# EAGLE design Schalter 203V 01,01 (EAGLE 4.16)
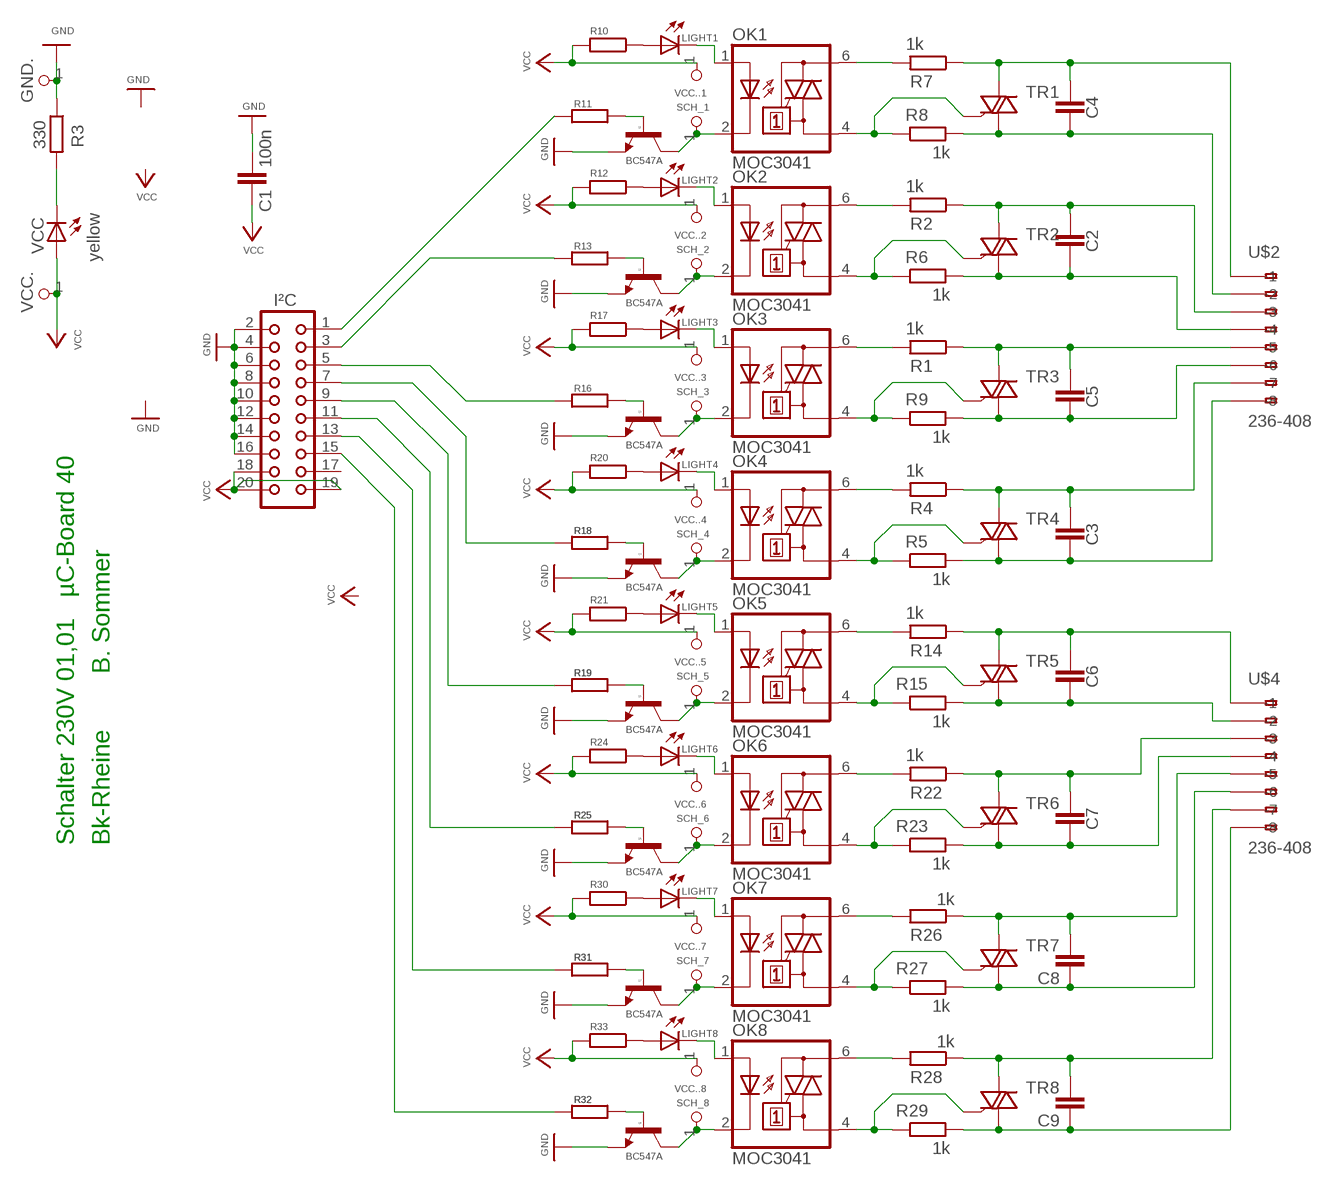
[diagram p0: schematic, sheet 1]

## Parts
C1  100n  C-EU025-030X050  [C025-030X050]
C2  C-EU075-052X106  [C075-052X106]
C3  C-EU075-052X106  [C075-052X106]
C4  C-EU075-052X106  [C075-052X106]
C5  C-EU075-052X106  [C075-052X106]
C6  C-EU075-052X106  [C075-052X106]
C7  C-EU075-052X106  [C075-052X106]
C8  C-EU075-052X106  [C075-052X106]
C9  C-EU075-052X106  [C075-052X106]
GND.  PINHD-1X1  [1X01]
I²C  CON20  [CON20]
LIGHT1  LED3MM  [LED3MM]
LIGHT2  LED3MM  [LED3MM]
LIGHT3  LED3MM  [LED3MM]
LIGHT4  LED3MM  [LED3MM]
LIGHT5  LED3MM  [LED3MM]
LIGHT6  LED3MM  [LED3MM]
LIGHT7  LED3MM  [LED3MM]
LIGHT8  LED3MM  [LED3MM]
OK1  MOC3041  IL410  [DIL06]
OK2  MOC3041  IL410  [DIL06]
OK3  MOC3041  IL410  [DIL06]
OK4  MOC3041  IL410  [DIL06]
OK5  MOC3041  IL410  [DIL06]
OK6  MOC3041  IL410  [DIL06]
OK7  MOC3041  IL410  [DIL06]
OK8  MOC3041  IL410  [DIL06]
Q1  BC547A  [TO92]
Q2  BC547A  [TO92]
Q3  BC547A  [TO92]
Q4  BC547A  [TO92]
Q5  BC547A  [TO92]
Q6  BC547A  [TO92]
Q7  BC547A  [TO92]
Q8  BC547A  [TO92]
R1  1k  R-EU_0204/7  [0204/7]
R2  1k  R-EU_0204/7  [0204/7]
R3  330  R-EU_0204/7  [0204/7]
R4  1k  R-EU_0204/7  [0204/7]
R5  1k  R-EU_0204/7  [0204/7]
R6  1k  R-EU_0204/7  [0204/7]
R7  1k  R-EU_0204/7  [0204/7]
R8  1k  R-EU_0204/7  [0204/7]
R9  1k  R-EU_0204/7  [0204/7]
R10  R-EU_0204/7  [0204/7]
R11  R-EU_0204/7  [0204/7]
R12  R-EU_0204/7  [0204/7]
R13  R-EU_0204/7  [0204/7]
R14  1k  R-EU_0204/7  [0204/7]
R15  1k  R-EU_0204/7  [0204/7]
R16  R-EU_0204/7  [0204/7]
R17  R-EU_0204/7  [0204/7]
R18  R-EU_0204/7  [0204/7]
R19  R-EU_0204/7  [0204/7]
R20  R-EU_0204/7  [0204/7]
R21  R-EU_0204/7  [0204/7]
R22  1k  R-EU_0204/7  [0204/7]
R23  1k  R-EU_0204/7  [0204/7]
R24  R-EU_0204/7  [0204/7]
R25  R-EU_0204/7  [0204/7]
R26  1k  R-EU_0204/7  [0204/7]
R27  1k  R-EU_0204/7  [0204/7]
R28  1k  R-EU_0204/7  [0204/7]
R29  1k  R-EU_0204/7  [0204/7]
R30  R-EU_0204/7  [0204/7]
R31  R-EU_0204/7  [0204/7]
R32  R-EU_0204/7  [0204/7]
R33  R-EU_0204/7  [0204/7]
SCH_1  PINHD-1X1  [1X01]
SCH_2  PINHD-1X1  [1X01]
SCH_3  PINHD-1X1  [1X01]
SCH_4  PINHD-1X1  [1X01]
SCH_5  PINHD-1X1  [1X01]
SCH_6  PINHD-1X1  [1X01]
SCH_7  PINHD-1X1  [1X01]
SCH_8  PINHD-1X1  [1X01]
TR1  BT138  [TO220XL]
TR2  BT138  [TO220XL]
TR3  BT138  [TO220XL]
TR4  BT138  [TO220XL]
TR5  BT138  [TO220XL]
TR6  BT138  [TO220XL]
TR7  BT138  [TO220XL]
TR8  BT138  [TO220XL]
U$2  236-408  [236-408]
U$4  236-408  [236-408]
VCC  yellow  LED3MM  [LED3MM]
VCC.  PINHD-1X1  [1X01]
VCC..1  PINHD-1X1  [1X01]
VCC..2  PINHD-1X1  [1X01]
VCC..3  PINHD-1X1  [1X01]
VCC..4  PINHD-1X1  [1X01]
VCC..5  PINHD-1X1  [1X01]
VCC..6  PINHD-1X1  [1X01]
VCC..7  PINHD-1X1  [1X01]
VCC..8  PINHD-1X1  [1X01]

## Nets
GND: C1.2 GND..1 I²C.2 I²C.4 I²C.6 I²C.8 I²C.10 I²C.12 I²C.14 I²C.16 Q1.1(E) Q2.1(E) Q3.1(E) Q4.1(E) Q5.1(E) Q6.1(E) Q7.1(E) Q8.1(E) R3.1
N$1: R3.2 VCC.K(C)
N$2: LIGHT2.A R12.1
N$3: OK4.2(C) Q4.3(C) SCH_4.1
N$4: LIGHT2.K(C) OK2.1(A)
N$5: OK2.2(C) Q1.3(C) SCH_2.1
N$6: Q1.2(B) R13.1
N$7: OK2.6(A2) R2.2
N$8: OK2.4(A1) R6.1 TR2.G
N$9: OK1.6(A2) R7.2
N$10: C2.1 R6.2 TR2.A1 U$2.A4(-4)
N$11: C2.2 R2.1 TR2.A2 U$2.A3(-3)
N$12: OK1.4(A1) R8.1 TR1.G
N$13: C4.1 R8.2 TR1.A1 U$2.A2(-2)
N$14: OK3.6(A2) R1.2
N$15: C4.2 R7.1 TR1.A2 U$2.A1(-1)
N$16: C5.2 R1.1 TR3.A2 U$2.A5(-5)
N$17: C5.1 R9.2 TR3.A1 U$2.A6(-6)
N$18: OK3.4(A1) R9.1 TR3.G
N$19: LIGHT1.K(C) OK1.1(A)
N$20: LIGHT1.A R10.1
N$21: OK1.2(C) Q2.3(C) SCH_1.1
N$22: Q2.2(B) R11.1
N$23: OK5.6(A2) R14.2
N$24: OK4.6(A2) R4.2
N$25: OK4.4(A1) R5.1 TR4.G
N$26: OK5.4(A1) R15.1 TR5.G
N$28: C6.2 R14.1 TR5.A2 U$4.A1(-1)
N$29: C6.1 R15.2 TR5.A1 U$4.A2(-2)
N$30: I²C.1 R11.2
N$31: I²C.3 R13.2
N$32: C3.2 R4.1 TR4.A2 U$2.A7(-7)
N$33: C3.1 R5.2 TR4.A1 U$2.A8(-8)
N$34: LIGHT3.A R17.1
N$35: LIGHT3.K(C) OK3.1(A)
N$36: Q4.2(B) R18.1
N$37: Q3.2(B) R16.1
N$38: OK3.2(C) Q3.3(C) SCH_3.1
N$39: I²C.5 R16.2
N$40: OK5.2(C) Q5.3(C) SCH_5.1
N$41: Q5.2(B) R19.1
N$42: I²C.7 R18.2
N$43: I²C.9 R19.2
N$44: LIGHT4.A R20.1
N$45: LIGHT4.K(C) OK4.1(A)
N$46: LIGHT5.A R21.1
N$47: LIGHT5.K(C) OK5.1(A)
N$48: OK6.6(A2) R22.2
N$49: C7.2 R22.1 TR6.A2 U$4.A3(-3)
N$50: OK6.4(A1) R23.1 TR6.G
N$51: C7.1 R23.2 TR6.A1 U$4.A4(-4)
N$52: LIGHT6.A R24.1
N$53: OK7.6(A2) R26.2
N$54: C8.2 R26.1 TR7.A2 U$4.A5(-5)
N$55: OK7.4(A1) R27.1 TR7.G
N$56: C8.1 R27.2 TR7.A1 U$4.A6(-6)
N$57: LIGHT6.K(C) OK6.1(A)
N$58: Q6.2(B) R25.1
N$59: OK6.2(C) Q6.3(C) SCH_6.1
N$60: OK8.6(A2) R28.2
N$61: C9.2 R28.1 TR8.A2 U$4.A7(-7)
N$62: OK8.4(A1) R29.1 TR8.G
N$63: C9.1 R29.2 TR8.A1 U$4.A8(-8)
N$64: LIGHT7.A R30.1
N$65: LIGHT8.A R33.1
N$66: LIGHT7.K(C) OK7.1(A)
N$67: Q7.2(B) R31.1
N$68: OK7.2(C) Q7.3(C) SCH_7.1
N$69: LIGHT8.K(C) OK8.1(A)
N$70: OK8.2(C) Q8.3(C) SCH_8.1
N$71: Q8.2(B) R32.1
N$72: I²C.13 R31.2
N$73: I²C.15 R32.2
N$74: I²C.11 R25.2
VCC: C1.1 I²C.18 I²C.19 I²C.20 R10.2 R12.2 R17.2 R20.2 R21.2 R24.2 R30.2 R33.2 VCC..1 VCC..1.1 VCC..2.1 VCC..3.1 VCC..4.1 VCC..5.1 VCC..6.1 VCC..7.1 VCC..8.1 VCC.A
Unconnected: I²C.17 U$2.B1(B-1) U$2.B2(B-2) U$2.B3(B-3) U$2.B4(B-4) U$2.B5(B-5) U$2.B6(B-6) U$2.B7(B-7) U$2.B8(B-8) U$4.B1(B-1) U$4.B2(B-2) U$4.B3(B-3) U$4.B4(B-4) U$4.B5(B-5) U$4.B6(B-6) U$4.B7(B-7) U$4.B8(B-8)

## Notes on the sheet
- Schalter 230V 01,01   µC-Board 40 | Bk-Rheine        B. Sommer

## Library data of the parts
C1-C9 = rcl:C-EU: CAPACITOR, European symbol
GND. SCH_1-SCH_8 VCC. VCC..1-VCC..8 = pinhead 02:PINHD-1X1: PIN HEADER
I²C = con-harting:CON20: CONNECTOR
LIGHT1-LIGHT8 VCC = led:LED: LED
OK1-OK8 = optocoupler:IL410: SIEMENS OPTO COUPLER
Q1-Q8 = transistor-npn:BC547*: NPN Transistor
R1-R33 = rcl:R-EU_: RESISTOR, European symbol
TR1-TR8 = triac:BT138
U$2 U$4 = con-wago255:236-408

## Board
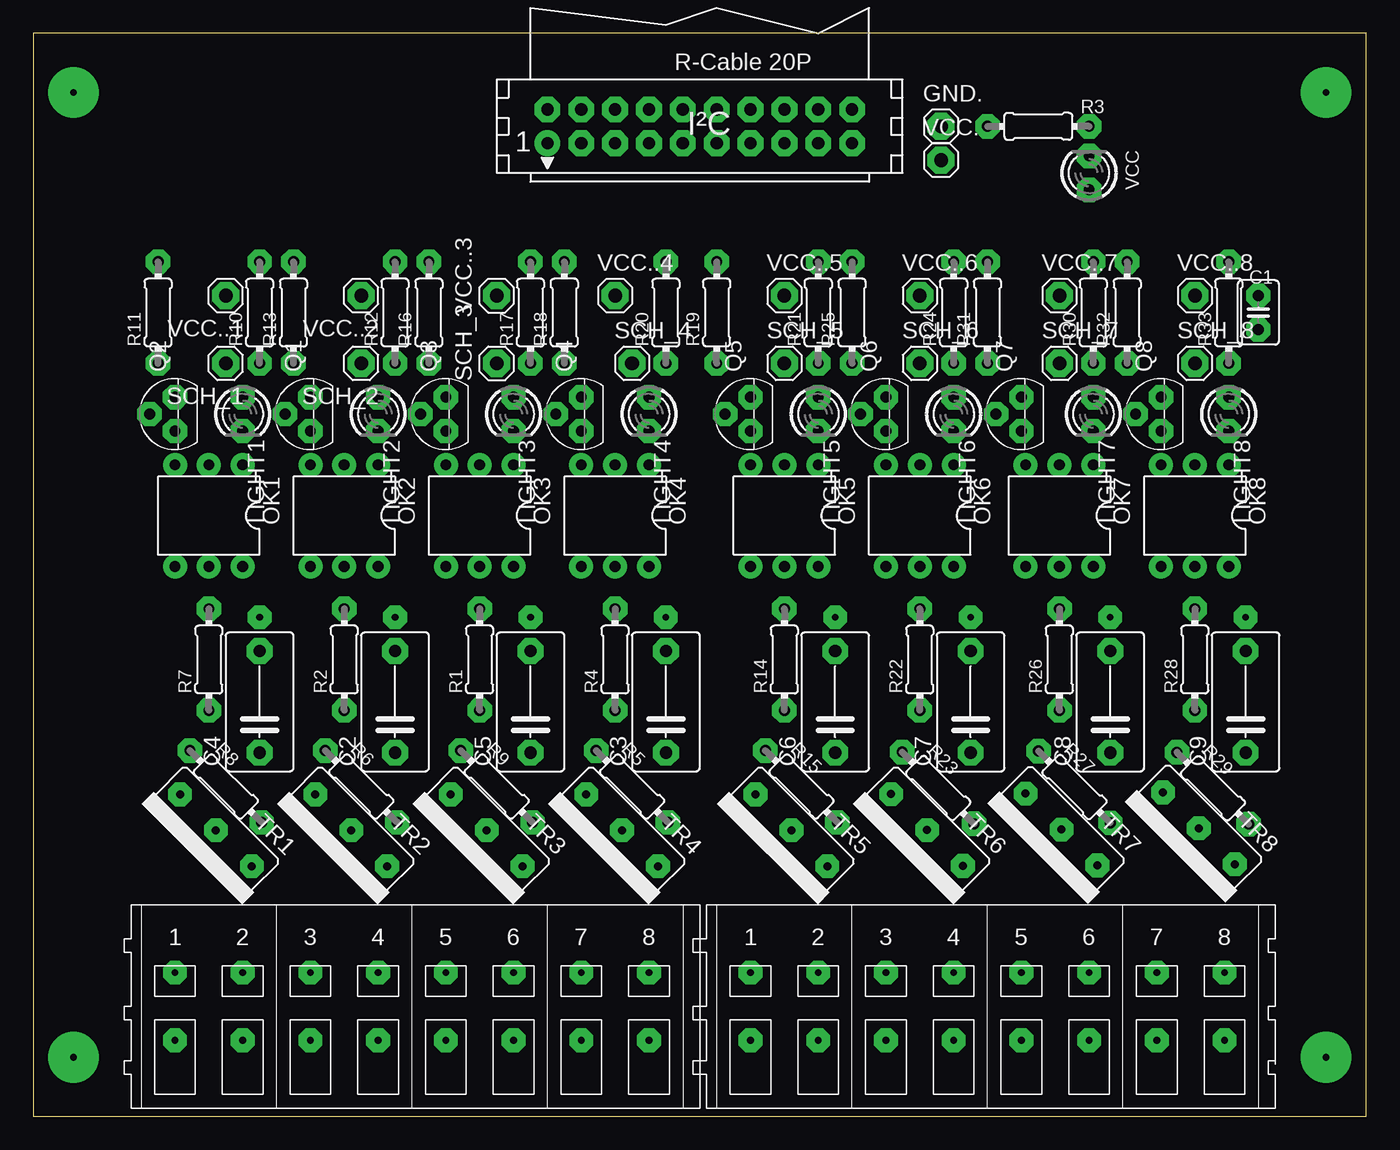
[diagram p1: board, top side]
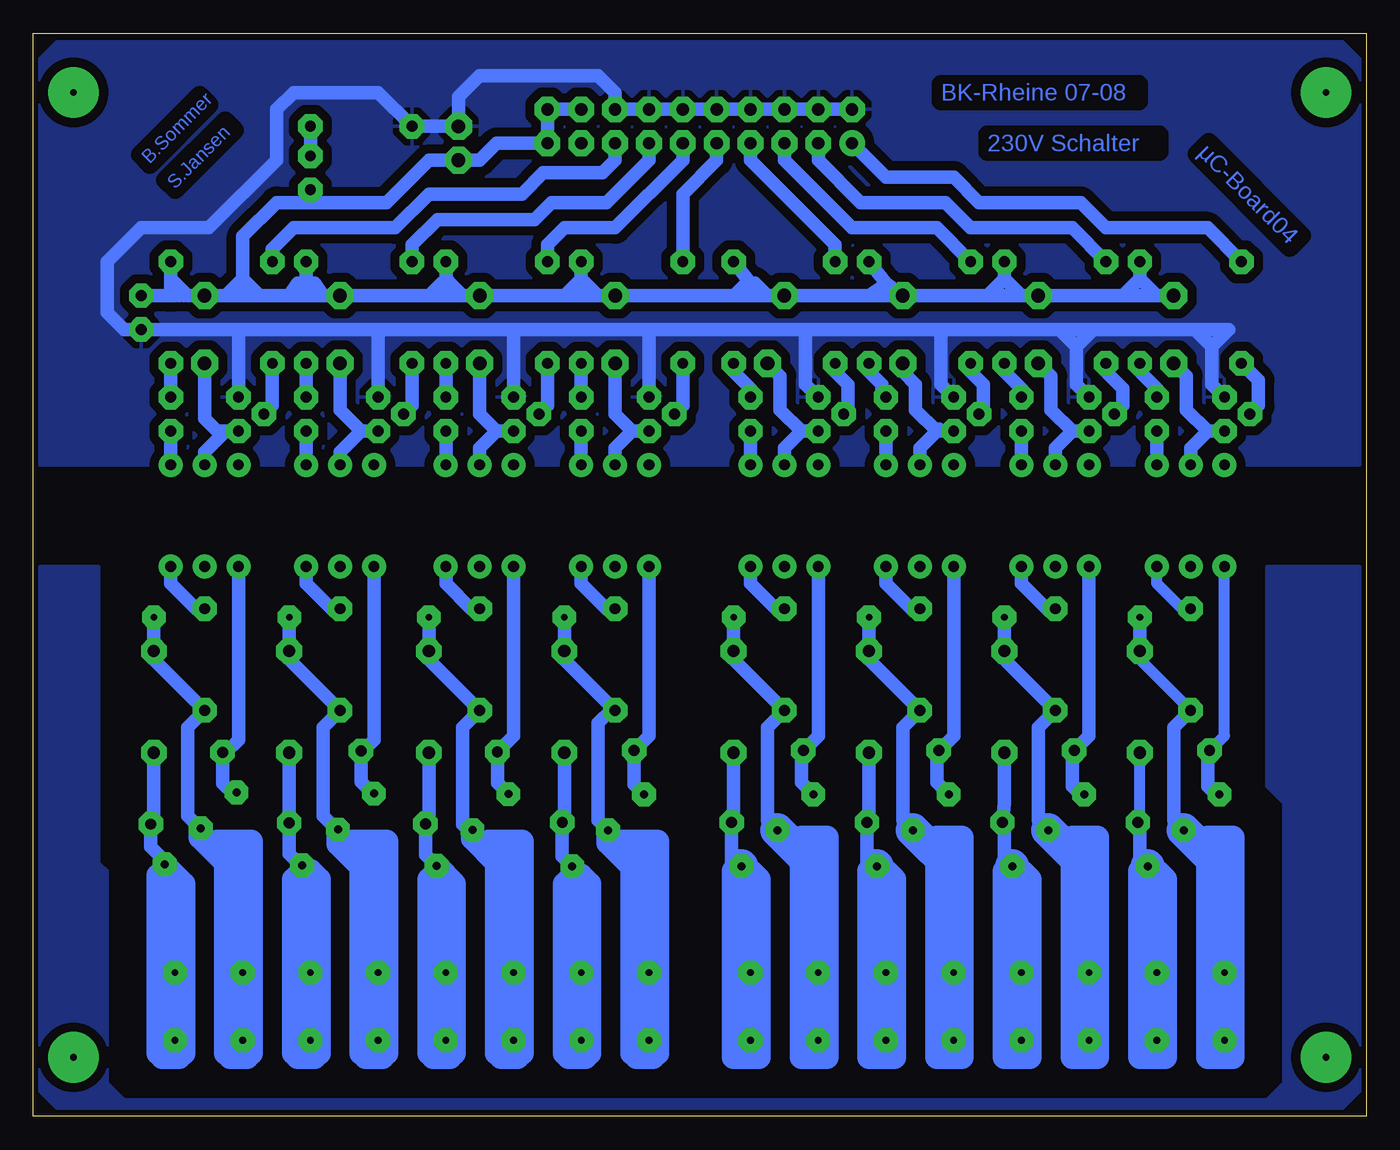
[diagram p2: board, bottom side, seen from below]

Size 100 x 81.27 mm. Coordinates in mm from the lower left corner, seen from the top.
Outline: 0,0 100,0 100,81.27 0,81.27 0,0
Copper layers (1*16): Top 0.035mm / dielectric 1.5mm / Bottom 0.035mm
Design rules "sommer_01_Ätzen": minimum track width 24mil, minimum drill 5mil, track to track 27mil, track to pad 27mil, pad to pad 10mil, via to via 10mil, smd to smd 8mil, copper to edge 0mil, drill to drill 25mil, minimum pad ring 20mil, minimum via ring 20mil, stop-mask expansion 4mil, vias tented up to drill 0mil, thermal gap 20mil

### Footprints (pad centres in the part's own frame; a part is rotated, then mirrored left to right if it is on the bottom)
C025-030X050 = drill 0.813 octagon: 1 -1.27,0; 2 1.27,0
C075-052X106 = drill 0.914 octagon: 1 -3.81,0; 2 3.81,0
1X01 = drill 1.016 octagon: 1 0,0
CON20 = drill 0.914 round: 1 -11.43,-1.27 | drill 0.914 octagon: 2 -11.43,1.27; 3 -8.89,-1.27; 4 -8.89,1.27; 5 -6.35,-1.27; 6 -6.35,1.27; 7 -3.81,-1.27; 8 -3.81,1.27; 9 -1.27,-1.27; 10 -1.27,1.27; 11 1.27,-1.27; 12 1.27,1.27; 13 3.81,-1.27; 14 3.81,1.27; 15 6.35,-1.27; 16 6.35,1.27; 17 8.89,-1.27; 18 8.89,1.27; 19 11.43,-1.27; 20 11.43,1.27
LED3MM = drill 0.813 octagon: A -1.27,0; K 1.27,0
DIL06 = drill 0.813 long: 1 -2.54,-3.81; 2 0,-3.81; 3 2.54,-3.81; 4 2.54,3.81; 5 0,3.81; 6 -2.54,3.81
TO92 = drill 0.813 octagon: 1 1.27,0; 2 0,1.905; 3 -1.27,0
0204/7 = drill 0.813 octagon: 1 -3.81,0; 2 3.81,0
TO220XL = drill 0.6 pad 1.778 octagon: A1 -3.81,-2.54; A2 0,-2.54; G 3.81,-2.54
236-408 = drill 0.5 pad 1.778 octagon: A1 -17.78,2.54; A2 -12.7,2.54; A3 -7.62,2.54; A4 -2.54,2.54; A5 2.54,2.54; A6 7.62,2.54; A7 12.7,2.54; A8 17.78,2.54; B1 -17.78,-2.54; B2 -12.7,-2.54; B3 -7.62,-2.54; B4 -2.54,-2.54; B5 2.54,-2.54; B6 7.62,-2.54; B7 12.7,-2.54; B8 17.78,-2.54

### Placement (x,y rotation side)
C1  91.91,60.32 270 top
C2  27.14,31.11 90 top
C3  47.46,31.11 90 top
C4  16.98,31.11 90 top
C5  37.3,31.11 90 top
C6  60.16,31.11 90 top
C7  70.32,31.11 90 top
C8  80.8,31.11 90 top
C9  90.96,31.11 90 top
GND.  68.1,74.29 0 top
I²C  50,74.29 0 top
LIGHT1  15.71,52.7 270 top
LIGHT2  25.87,52.7 270 top
LIGHT3  36.03,52.7 270 top
LIGHT4  46.19,52.7 270 top
LIGHT5  58.89,52.7 270 top
LIGHT6  69.05,52.7 270 top
LIGHT7  79.53,52.7 270 top
LIGHT8  89.69,52.7 270 top
OK1  13.17,45.08 180 top
OK2  23.33,45.08 180 top
OK3  33.49,45.08 180 top
OK4  43.65,45.08 180 top
OK5  56.35,45.08 180 top
OK6  66.51,45.08 180 top
OK7  76.99,45.08 180 top
OK8  87.15,45.08 180 top
Q1  20.79,52.7 90 top
Q2  10.63,52.7 90 top
Q3  30.95,52.7 90 top
Q4  41.11,52.7 90 top
Q5  53.81,52.7 90 top
Q6  63.97,52.7 90 top
Q7  74.13,52.7 90 top
Q8  84.61,52.7 90 top
R1  33.49,34.29 90 top
R2  23.33,34.29 90 top
R3  75.4,74.29 0 top
R4  43.65,34.29 90 top
R5  44.92,24.76 315 top
R6  24.6,24.76 315 top
R7  13.17,34.29 90 top
R8  14.44,24.76 315 top
R9  34.76,24.76 315 top
R10  16.98,60.32 90 top
R11  9.36,60.32 90 top
R12  27.14,60.32 90 top
R13  19.52,60.32 90 top
R14  56.35,34.29 90 top
R15  57.62,24.76 315 top
R16  29.68,60.32 90 top
R17  37.3,60.32 90 top
R18  39.84,60.32 90 top
R19  51.27,60.32 90 top
R20  47.46,60.32 90 top
R21  58.89,60.32 90 top
R22  66.51,34.29 90 top
R23  67.88,24.65 315 top
R24  69.05,60.32 90 top
R25  61.43,60.32 90 top
R26  76.99,34.29 90 top
R27  78.11,24.72 315 top
R28  87.15,34.29 90 top
R29  88.49,24.63 315 top
R30  79.53,60.32 90 top
R31  71.59,60.32 90 top
R32  82.07,60.32 90 top
R33  89.69,60.32 90 top
SCH_1  14.44,56.51 180 top
SCH_2  24.6,56.51 180 top
SCH_3  34.76,56.51 90 top
SCH_4  44.92,56.51 0 top
SCH_5  56.35,56.51 0 top
SCH_6  66.51,56.51 0 top
SCH_7  76.99,56.51 0 top
SCH_8  87.15,56.51 0 top
TR1  11.9,19.68 135 top
TR2  22.06,19.68 135 top
TR3  32.22,19.68 135 top
TR4  42.38,19.68 135 top
TR5  55.08,19.68 135 top
TR6  65.26,19.7 135 top
TR7  75.35,19.73 135 top
TR8  85.65,19.83 135 top
U$2  28.41,8.25 0 top
U$4  71.59,8.25 0 top
VCC  79.21,70.8 90 top
VCC.  68.1,71.75 0 top
VCC..1  14.44,61.59 180 top
VCC..2  24.6,61.59 180 top
VCC..3  34.76,61.59 90 top
VCC..4  43.65,61.59 0 top
VCC..5  56.35,61.59 0 top
VCC..6  66.51,61.59 0 top
VCC..7  76.99,61.59 0 top
VCC..8  87.15,61.59 0 top

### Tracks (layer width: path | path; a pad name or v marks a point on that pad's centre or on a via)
GND
  Bottom 1.016: Q2.1 11.58,54.92 11.58,57.78 | 11.58,57.78 12.85,59.05 | 12.85,59.05 10.31,59.05 11.58,57.78 | Q1.1 21.74,54.92 21.74,57.78 | 20.47,59.05 21.74,57.78 | 12.85,59.05 20.47,59.05 | 20.47,59.05 23.01,59.05 | 21.74,57.78 23.01,59.05 | GND..1 68.1,76.51 66.51,78.1 57.62,78.1 56.35,76.83 I²C.16 I²C.14 I²C.12 I²C.10 I²C.8 I²C.6 I²C.4 I²C.2 | GND..1 67.78,74.29 | 23.01,59.05 31.9,59.05 | 53.81,59.05 54.13,59.05 | 52.54,59.05 53.81,59.05 | 52.54,59.05 52.22,59.05 | 31.9,59.05 42.06,59.05 | 63.97,59.05 Q6.1 | 74.13,59.05 Q7.1 | 63.97,59.05 63.34,59.05 | 63.97,59.05 64.29,59.05 | 84.61,59.05 Q8.1 | 74.13,59.05 84.61,59.05 | Q3.1 31.9,54.92 31.9,59.05 | Q4.1 42.06,54.92 42.06,59.05 | 42.06,59.05 52.54,59.05 | 53.81,59.05 Q5.1 | 53.81,59.05 63.97,59.05 | 63.97,59.05 74.13,59.05 | 84.61,59.05 C1.2 93.18,59.05 94.45,60.32 94.45,64.13 91.91,66.67 86.83,66.67 81.75,71.75 81.75,75.56 80.48,76.83 74.13,76.83 R3.1 GND..1
  pour Bottom: 0.47,79.37 1.74,80.64 98.26,80.64 99.53,79.37 99.53,48.89 0.47,48.89
N$1
  Bottom 1.016: 79.21,71.75 VCC.K R3.2
N$2
  Bottom 1.016: R12.1 27.14,55.88 25.87,54.61 LIGHT2.A
N$3
  Bottom 1.016: SCH_4.1 43.97,55.56 43.97,53.02 42.38,51.43 | Q4.3 42.38,51.43 | OK4.2 43.65,50.16 42.38,51.43
N$4
  Bottom 1.016: OK2.1 LIGHT2.K
N$5
  Bottom 1.016: OK2.2 23.33,50.16 22.06,51.43 | Q1.3 22.06,51.43 | SCH_2.1 23.65,55.56 23.65,53.02 22.06,51.43
N$6
  Bottom 1.016: Q1.2 18.25,53.34 18.25,54.61 19.52,55.88 R13.1
N$7
  Bottom 1.016: OK2.6 25.87,40 23.96,38.1 R2.2
N$8
  Bottom 1.016: OK2.4 20.79,28.57 R6.1 22.06,27.3 22.06,24.76 21.47,24.17 TR2.G
N$9
  Bottom 0.813: OK1.6 15.71,40 13.81,38.1 R7.2
N$10
  Bottom 1.016: C2.1 27.14,23.49 R6.2 27.14,21.91 27.14,19.37 TR2.A1
  Bottom 1.778: 25.87,12.06 27.14,12.06 27.14,10.79 | 27.14,10.79 27.14,4.44 25.87,4.44 | 25.87,4.44 25.23,4.44 25.23,17.77 26.5,19.04 | 27.14,10.79 27.14,18.41 | 27.14,10.79 U$2.A4 | 25.87,4.44 25.87,17.14
  Bottom 2.54: TR2.A1 26.55,12.74 25.87,12.06
N$11  (via drill 0.5 pad 1.78)
  Bottom 1.016: TR2.A2 24.6,22.22 24.6,29.2 R2.1 27.14,34.29 C2.2 v27.14,37.46
  Bottom 1.778: 22.06,4.44 22.06,12.06 20.79,12.06 U$2.A3 | 20.79,4.44 20.15,4.44 20.15,20.95 22.06,20.95 22.06,4.44 | 20.79,4.44 22.06,4.44 | 20.79,4.44 20.79,18.41
  Bottom 2.54: TR2.A2 20.79,18.41 20.79,12.06
N$12
  Bottom 0.813: R8.1 11.9,27.3 10.63,28.57 OK1.4
  Bottom 1.016: 11.64,27.04 11.9,27.3 11.9,24.76 11.31,24.17 TR1.G
N$13
  Bottom 0.813: R8.2 16.98,22.22 C4.1
  Bottom 1.016: TR1.A1 16.98,19.37 16.98,21.91 R8.2
  Bottom 1.778: 15.71,12.06 16.98,12.06 16.98,10.79 | 16.98,10.79 16.98,4.44 15.71,4.44 | 15.71,4.44 15.08,4.44 15.08,17.77 16.34,19.04 16.98,18.41 16.98,10.79 | 16.98,10.79 U$2.A2 | 15.71,4.44 15.71,14.6
  Bottom 2.54: TR1.A1 16.39,12.74 15.71,12.06
N$14
  Bottom 1.016: OK3.6 36.03,40 34.12,38.1 R1.2
N$15  (via drill 0.5 pad 1.78)
  Bottom 0.813: C4.2 16.98,34.29 R7.1
  Bottom 1.016: TR1.A2 14.44,22.22 14.44,29.2 R7.1 | C4.2 v16.98,37.46
  Bottom 1.778: 11.9,12.06 10.63,12.06 U$2.A1 | 11.9,12.06 11.9,19.68 11.9,20.95 10,20.95 10,4.44 10.63,4.44 | 10.63,4.44 11.9,4.44 11.9,12.06 | 10.63,4.44 10.63,18.41
  Bottom 2.54: TR1.A2 11.9,19.68 10.63,18.41 10.63,12.06
N$16  (via drill 0.5 pad 1.78)
  Bottom 1.016: TR3.A2 34.76,22.22 34.76,29.2 R1.1 37.3,34.29 C5.2 v37.3,37.46
  Bottom 1.778: 32.22,4.44 32.22,12.06 30.95,12.06 U$2.A5 | 30.95,4.44 30.31,4.44 30.31,20.95 32.22,20.95 32.22,4.44 | 30.95,4.44 32.22,4.44 | 30.95,4.44 30.95,18.41
  Bottom 2.54: TR3.A2 30.95,18.41 30.95,12.06
N$17
  Bottom 1.016: TR3.A1 36.71,19.09 37.45,19.2 R9.2 37.3,22.22 C5.1
  Bottom 1.778: 37.3,4.44 37.3,12.06 36.03,12.06 U$2.A6 | 36.03,4.44 35.39,4.44 35.39,17.77 36.66,19.04 37.3,18.41 37.3,4.44 | 36.03,4.44 37.3,4.44 | 36.03,4.44 36.03,15.87
  Bottom 2.54: TR3.A1 36.71,12.74 36.03,12.06
N$18
  Bottom 1.016: TR3.G 32.22,25.07 32.22,27.3 R9.1 30.95,28.57 OK3.4
N$19
  Bottom 1.016: OK1.1 LIGHT1.K
N$20
  Bottom 1.016: R10.1 16.98,55.88 15.71,54.61 LIGHT1.A
N$21
  Bottom 1.016: SCH_1.1 13.49,55.56 13.49,53.02 11.9,51.43 | Q2.3 11.9,51.43 | 11.9,51.43 13.17,50.16 OK1.2
N$22
  Bottom 1.016: Q2.2 8.09,53.34 8.09,55.24 R11.1
N$23
  Bottom 1.016: OK5.6 58.89,40 56.98,38.1 R14.2
N$24
  Bottom 1.016: OK4.6 46.19,40 44.28,38.1 R4.2
N$25
  Bottom 1.016: TR4.G 42.38,25.07 42.38,27.3 R5.1 41.11,28.57 OK4.4
N$26
  Bottom 1.016: R15.1 55.08,27.3 | R15.1 | OK5.4 53.81,28.57 R15.1 | TR5.G 54.93,24.92 R15.1
N$27
  pour Bottom: 1.74,79.37 98.26,79.37 98.26,48.89 1.74,48.89
N$28  (via drill 0.5 pad 1.78)
  Bottom 1.016: TR5.A2 57.62,22.22 57.62,29.52 56.67,30.47 R14.1 60.48,34.6 C6.2 v60.16,37.46
  Bottom 1.778: TR5.A2 56.88,20.52 55.08,18.73 55.08,4.76 54.76,4.44 53.49,4.44 53.17,4.76 53.17,20.63 56.67,20.63 55.4,19.68 53.81,19.36 U$4.A1 | U$4.A1 53.81,6.03 54.13,5.71 54.13,10.47 U$4.A1
N$29
  Bottom 1.016: R15.2 60.16,22.22 C6.1 | R15.2 | 59.52,18.73 TR5.A1 | TR5.A1 | R15.2 60.31,19.52 TR5.A1
  Bottom 1.778: 59.52,18.73 59.52,18.09 60.16,17.46 60.16,4.76 59.84,4.44 58.57,4.44 58.25,4.76 58.25,17.46 58.89,18.09 U$4.A2 58.89,10.16 | 58.89,10.16 58.89,6.03 59.21,5.71 59.21,9.84 58.89,10.16
N$30
  Bottom 1.016: R11.2 11.9,66.67 19.52,66.67 21.42,68.57 29.04,68.57 30.95,70.48 36.03,70.48 I²C.1
N$31
  Bottom 1.016: R13.2 22.06,66.67 29.68,66.67 31.58,68.57 37.94,68.57 41.11,71.75 I²C.3
N$32  (via drill 0.5 pad 1.78)
  Bottom 1.016: TR4.A2 44.92,22.22 44.92,29.2 R4.1 47.46,34.29 C3.2 v47.46,37.46
  Bottom 1.778: 42.38,4.44 42.38,12.06 41.11,12.06 U$2.A7 | 41.11,4.44 40.48,4.44 40.48,20.95 42.38,20.95 41.11,19.68 42.38,19.68 42.38,4.44 | 41.11,4.44 42.38,4.44 | 41.11,4.44 41.11,18.41
  Bottom 2.54: TR4.A2 42.38,19.68 41.11,18.41 41.11,12.06
N$33
  Bottom 1.016: TR4.A1 46.87,19.09 47.61,19.2 R5.2 47.46,22.22 C3.1
  Bottom 1.778: 47.46,4.44 47.46,12.06 46.19,12.06 U$2.A8 | 46.19,4.44 47.46,4.44 | 46.19,4.44 45.55,4.44 45.55,17.77 46.82,19.04 47.46,18.41 47.46,4.44 | 46.19,4.44 46.19,14.6
  Bottom 2.54: TR4.A1 46.87,12.74 46.19,12.06
N$34
  Bottom 1.016: R17.1 37.3,55.88 36.35,54.92 36.35,54.29 LIGHT3.A
N$35
  Bottom 1.016: OK3.1 LIGHT3.K
N$36
  Bottom 1.016: R18.1 39.84,55.88 38.89,54.92 38.89,53.02 Q4.2
N$37
  Bottom 1.016: R16.1 29.68,55.88 28.73,54.92 28.73,53.02 Q3.2
N$38
  Bottom 1.016: 32.22,51.43 32.06,51.59 | 32.06,51.59 | OK3.2 33.49,50.16 32.22,51.43 | 32.22,51.43 32.06,51.59 | SCH_3.1 34.76,55.88 33.81,54.92 33.81,53.02 32.22,51.43 | 32.22,51.43 Q3.3
N$39
  Bottom 1.016: R16.2 32.22,66.67 38.57,66.67 43.65,71.75 I²C.5
N$40
  Bottom 1.016: SCH_5.1 56.35,52.7 55.08,51.43 | 55.08,51.43 Q5.3 | OK5.2 56.35,50.16 55.08,51.43
N$41
  Bottom 1.016: Q5.2 51.27,53.34 R19.1
N$42
  Bottom 1.016: R18.2 39.84,65.4 46.19,71.75 I²C.7
N$43
  Bottom 1.016: R19.2 51.27,69.21 48.73,71.75 I²C.9
N$44
  Bottom 1.016: LIGHT4.A 46.19,54.61 47.46,55.88 R20.1
N$45
  Bottom 1.016: OK4.1 LIGHT4.K
N$46
  Bottom 1.016: LIGHT5.A R21.1
N$47
  Bottom 1.016: OK5.1 LIGHT5.K
N$48
  Bottom 1.016: OK6.6 69.05,40 67.14,38.1 R22.2
N$49  (via drill 0.5 pad 1.78)
  Bottom 1.016: TR6.A2 67.37,21.49 67.78,21.9 67.78,29.2 R22.1 70.64,34.6 C7.2 v70.32,37.46
  Bottom 1.778: TR6.A2 67.05,20.86 65.24,19.04 65.24,4.76 64.92,4.44 63.65,4.44 63.34,4.76 63.34,20.63 65.88,20.63 65.88,20.31 64.61,19.04 64.61,6.34 64.29,6.03 64.29,10.47 U$4.A3
N$50
  Bottom 1.016: R23.1 65.24,27.3 | R23.1 65.19,25.02 TR6.G | OK6.4 63.97,28.57 R23.1
N$51
  Bottom 1.016: C7.1 70.32,22.22 R23.2 70.57,19.62 TR6.A1
  Bottom 1.778: TR6.A1 69.75,18.35 70.32,17.77 70.32,4.76 70,4.44 68.73,4.44 68.41,4.76 68.41,17.46 69.69,18.73 69.69,9.84 | U$4.A4 69.05,10.47 69.69,9.84 | 69.69,9.84 69.69,5.71
N$52
  Bottom 1.016: LIGHT6.A R24.1
N$53
  Bottom 1.016: OK7.6 79.53,40 77.62,38.1 R26.2
N$54  (via drill 0.5 pad 1.78)
  Bottom 1.016: TR7.A2 77.25,21.53 78.26,22.54 78.26,29.2 R26.1 81.11,34.6 C8.2 80.8,37.14 80.48,37.46 v80.8,37.46
  Bottom 1.778: TR7.A2 77.14,20.47 75.4,18.73 75.4,4.76 75.08,4.44 73.81,4.44 73.5,4.76 73.5,20.63 76.03,20.63 74.77,19.36 74.77,10.16 | 74.77,10.16 74.77,5.39 | 74.77,10.16 U$4.A5
N$55
  Bottom 1.016: OK7.4 74.45,28.25 75.4,27.3 75.42,27.32 R27.1 75.42,25.09 74.55,24.22 TR7.G
N$56
  Bottom 1.016: C8.1 80.8,22.22 80.8,22.21 R27.2 80.8,19.69 79.84,18.73 79.84,18.74 TR7.A1
  Bottom 1.778: 79.84,18.73 79.84,18.41 80.48,17.77 80.48,4.76 80.16,4.44 78.89,4.44 78.58,4.76 78.58,17.77 79.21,18.41 U$4.A6 | U$4.A6 79.21,6.03 79.53,5.71 79.53,10.47 U$4.A6
N$57
  Bottom 1.016: OK6.1 LIGHT6.K
N$58
  Bottom 1.016: R25.1 61.43,53.34 Q6.2
N$59
  Bottom 1.016: SCH_6.1 66.51,52.7 65.24,51.43 | Q6.3 65.24,51.43 | OK6.2 66.51,50.16 65.24,51.43
N$60
  Bottom 1.016: OK8.6 89.69,40 87.78,38.1 R28.2
N$61  (via drill 0.5 pad 1.78)
  Bottom 1.016: TR8.A2 87.45,21.6 87.47,21.58 88.42,22.54 88.42,29.2 R28.1 91.28,34.6 C9.2 90.96,37.14 90.64,37.46 v90.96,37.46
  Bottom 1.778: 87.47,21.58 87.47,20.95 85.56,19.04 85.56,4.76 85.24,4.44 83.97,4.44 83.66,4.76 83.66,20.63 86.19,20.63 84.92,19.36 84.92,6.03 84.61,5.71 84.61,10.47 U$4.A7
N$62
  Bottom 1.016: OK8.4 84.61,28.25 85.56,27.3 85.58,27.32 R29.1 85.8,25 84.92,24.12 84.75,24.29 TR8.G
N$63
  Bottom 1.016: C9.1 90.96,21.9 90.99,21.93 R29.2 91.19,20.23 90,19.04 90.12,18.93 TR8.A1
  Bottom 1.778: 90.12,18.93 90.12,18.61 90.64,18.09 90.64,4.76 90.32,4.44 89.05,4.44 88.73,4.76 88.73,17.46 90,18.73 90,6.03 89.69,5.71 89.69,11.11 U$4.A8
N$64
  Bottom 1.016: LIGHT7.A R30.1
N$65
  Bottom 1.016: LIGHT8.A R33.1
N$66
  Bottom 1.016: OK7.1 LIGHT7.K
N$67
  Bottom 1.016: R31.1 71.59,53.34 Q7.2
N$68
  Bottom 1.016: SCH_7.1 76.99,53.02 75.4,51.43 | Q7.3 75.4,51.43 | OK7.2 76.99,49.84 75.4,51.43
N$69
  Bottom 1.016: OK8.1 LIGHT8.K
N$70
  Bottom 1.016: SCH_8.1 87.15,52.38 86.19,51.43 85.88,51.43 | 85.88,51.43 Q8.3 | 85.88,51.43 85.88,51.11 87.15,49.84 OK8.2
N$71
  Bottom 1.016: R32.1 82.07,53.34 Q8.2
N$72
  Bottom 1.016: I²C.13 53.81,71.75 56.98,68.57 61.11,68.57 62.38,67.3 69.69,67.3 71.59,65.4 71.59,64.45 R31.2
N$73
  Bottom 1.016: I²C.15 56.35,71.75 57.3,70.8 61.75,70.8 63.34,69.21 70.32,69.21 72.86,66.67 80.48,66.67 82.07,65.08 R32.2
N$74
  Bottom 1.016: I²C.11 51.27,71.75 56.35,66.67 60.16,66.67 61.43,65.4 R25.2
N$75
  pour Bottom: 0.47,41.27 7.46,41.27 7.46,24.76 6.18,23.49 6.18,2.54 7.46,1.27 93.18,1.27 94.45,2.54 94.45,18.41 95.08,19.04 95.08,41.27 99.53,41.27 99.53,1.9 98.26,0.63 1.74,0.63 0.47,1.9
N$76  (via drill 0.5 pad 3.81)
  other vias: 3.01,76.83
N$77  (via drill 0.5 pad 3.81)
  other vias: 96.99,76.83
N$78  (via drill 0.5 pad 3.81)
  other vias: 3.01,4.44
N$79  (via drill 0.5 pad 3.81)
  other vias: 96.99,4.44
VCC
  Bottom 1.016: 16.98,62.86 15.71,61.59 VCC..1.1 18.25,61.59 | 16.98,62.86 R10.2 | 27.14,62.86 R12.2 | 25.87,61.59 27.14,62.86 | 25.87,61.59 VCC..2.1 18.25,61.59 | 18.25,61.59 16.98,62.86 | 25.87,61.59 28.41,61.59 | 27.14,62.86 28.41,61.59 | 28.41,61.59 VCC..3.1 | 57.62,61.59 VCC..5.1 44.92,61.59 | R21.2 58.89,62.86 58.25,62.23 | 67.78,61.59 VCC..6.1 60.16,61.59 | 68.89,62.7 69.05,62.86 R24.2 | 79.37,62.7 79.53,62.86 R30.2 | I²C.18 I²C.20 I²C.19 65.24,73.02 66.51,71.75 67.78,71.75 | 67.78,71.75 VCC..1 | 89.69,62.54 R33.2 89.69,62.86 88.42,61.59 VCC..8.1 85.56,61.59 | 89.37,62.23 88.73,61.59 | 89.69,62.54 89.37,62.23 | 89.69,62.54 89.69,62.23 89.05,61.59 89.05,61.91 89.37,62.23 | 89.37,62.23 90,61.59 | 90,61.59 89.37,61.59 | 90,61.59 C1.1 | VCC..3.1 37.3,61.59 | 37.3,61.59 VCC..4.1 44.92,61.59 | 37.3,61.59 36.35,62.23 VCC..3.1 | VCC..3.1 35.39,61.91 | R17.2 36.03,62.54 VCC..3.1 | 44.92,61.59 45.87,62.54 46.19,62.54 | 47.14,61.91 46.51,62.54 46.19,62.54 | 46.19,62.54 R20.2 | 57.62,61.59 58.89,61.59 | 57.62,61.59 58.25,62.23 | 58.25,62.23 59.21,62.54 60.16,61.59 | 58.89,61.59 60.16,61.59 | 58.89,61.59 58.25,62.23 | 70.32,61.59 VCC..7.1 78.26,61.59 | 67.78,61.59 68.73,62.54 69.37,62.54 70.32,61.59 | 69.05,61.59 70.32,61.59 | 67.78,61.59 69.05,61.59 | 68.89,62.7 69.05,62.54 69.05,61.59 | 68.89,62.7 | 80.8,61.59 83.02,61.59 | 83.02,61.59 84.29,61.59 | 84.29,61.59 85.56,61.59 | 78.26,61.59 78.89,62.54 80.16,62.54 80.8,61.59 | 79.53,61.59 80.8,61.59 | 78.26,61.59 79.53,61.59 | 79.37,62.7 79.53,62.54 79.53,61.59 | 79.37,62.7 | 67.78,71.75 70.32,71.75 73.5,68.57 79.21,68.57 | 79.21,68.57 81.75,68.57 84.29,66.03 84.29,62.86 | 84.29,61.59 84.29,62.86 | 83.02,61.59 84.29,62.86
  Bottom 1.016: 84.29,62.86 85.56,61.59 | 79.21,68.57 VCC.A

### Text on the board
Bottom: BK-Rheine 07-08 | µC-Board04 | 230V Schalter | B.Sommer | S.Jansen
